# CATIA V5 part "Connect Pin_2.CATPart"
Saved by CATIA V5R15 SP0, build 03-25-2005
Part number: Connect Pin_2
Material "Light Green": density 7860 kg/m3, Young's modulus 2e+11 Pa, Poisson ratio 0.266
Bounding box of the stored display mesh (mm): x -29 to 29, y -75 to 79, z -29 to 29
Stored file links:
  E:\#01 CATIA Lecture Materials\#06 DMU\#11 DMU Page01 KIN EX11\Connect Pin_2.CATPart
  E:\V5_education\CATIA Data\KIN\Under Motor\Shaft_2.CATPart
  C:\Program Files\Dassault Systemes\B20\win_b64\startup\materials\Catalog.CATMaterial
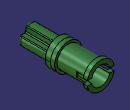
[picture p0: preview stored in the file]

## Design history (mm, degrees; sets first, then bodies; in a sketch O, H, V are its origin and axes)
Body1 (main body), material "Light Green"
  Sketch1 on xy-plane, origin (0, 0, 0), H (1, 0, 0), V (0, 1, 0)
    point P1 (0, 79)
    line L1 (0, 79) -> (29, 79)
    line L2 (29, 79) -> (29, 70)
    line L3 (29, 70) -> (24, 70)
    line L4 (24, 70) -> (24, 9)
    line L5 (24, 9) -> (29, 9)
    point P6 (29, 9)
    line L6 (29, 9) -> (29, 0)
    point P7 (29, 0)
    point P8 (29, 0)
    axis line L7 (0, -92.0572) -> (0, 94.0849)
    point P9 (0, -92.0572)
    line L8 (29, 0) -> (0, 0)
    distance L1 H = 79
    length L2 = 9
    length L6 = 9
    distance L2 V = 29
    distance L4 V = 24
    coincidence: P1 V, P6 L2, P7 H, P9 V, P7 P8
    horizontal: L1 H, L3 H, L5 H, L8 H
    vertical: L2 V, L4 V, L6 V, L7 V
    symmetry: P7 P8 H
  Shaft1: profile Sketch1, axis Sketch1.L7, angle 360
  Sketch2 on zx-plane, origin (0, 0, 0), H (1, 0, 0), V (0, 0, 1)
    circle A1 centre (0, 0) radius 20
    radius A1 = 20
  Pocket1: profile Sketch2, direction (0, 1, 0), through (limit type 3), opposite side length -9
  Sketch3 on yz-plane, origin (0, 0, 0), H (0, 1, 0), V (0, 0, 1)
    line L1 (50, 5) -> (79, 5)
    line L2 (79, 5) -> (79, -5)
    line L3 (79, -5) -> (50, -5)
    line L4 (50, -5) -> (50, 5)
    reference intersected line E1 (79, 29) -> (79, -29) from face of Shaft1 from Sketch1.L1
    distance L4 V = 50
    distance L3 L1 = 10
    horizontal: L1 H, L3 H
    vertical: L2 V, L4 V
    symmetry: L3 L1 H
    coincidence: L2 E1
  Pocket2: profile Sketch3, direction (-1, 0, 0), through (limit type 3), opposite side through (limit type 3)
  Sketch4 on face of Shaft1 from Sketch1.L8, origin (0, 0, 0), H (1, 0, 0), V (0, 0, 1)
    arc A1 centre (0, 0) radius 23.5 from (21.603, -9.25) to (21.603, 9.25) ccw
    line L1 (-21.603, 9.25) -> (-9.25, 9.25)
    line L2 (21.603, -9.25) -> (9.25, -9.25)
    line L3 (9.25, 21.603) -> (9.25, 9.25)
    line L4 (-9.25, -21.603) -> (-9.25, -9.25)
    point P4 (-9.25, -21.603)
    arc A2 centre (0, 0) radius 23.5 from (-9.25, -21.603) to (9.25, -21.603) ccw
    point P6 (-21.603, 9.25)
    arc A3 centre (0, 0) radius 23.5 from (-21.603, 9.25) to (-21.603, -9.25) ccw
    point P8 (9.25, 21.603)
    arc A4 centre (0, 0) radius 23.5 from (9.25, 21.603) to (-9.25, 21.603) ccw
    point P9 (-9.25, 9.25)
    line L5 (9.25, 9.25) -> (21.603, 9.25)
    line L6 (9.25, -9.25) -> (9.25, -21.603)
    line L7 (-9.25, 9.25) -> (-9.25, 21.603)
    point P12 (-9.25, -9.25)
    line L8 (-9.25, -9.25) -> (-21.603, -9.25)
    radius A1 = 23.5
    distance L1 L2 = 18.5
    distance H L1 = 9.25
    distance L3 L4 = 18.5
    distance V L3 = 9.25
    horizontal: L1 H, L2 H, L5 H, L8 H
    vertical: L3 V, L4 V, L6 V, L7 V
    coincidence: A1 P4, A1 A2, A1 P6, A1 A3, A1 P8, A1 A4, L4 P9, L1 L5, L3 L6, L2 P12, L4 L7, L2 L8
  Sketch5 on face of Shaft1 from Sketch1.L8, origin (0, 0, 0), H (1, 0, 0), V (0, 0, 1)
    circle A1 centre (0, 0) radius 29
    reference projected circle E1 centre (0, 0) radius 29 from edge [face of Shaft1 from Sketch1.L8 | face of Shaft1 from Sketch1.L6]
    coincidence: A1 E1
  Pad1: profile Sketch5, direction (0, -1, 0), length 11.4
  Pad2: profile Sketch4, direction (0, -1, 0), length 75
  Fillet1: radius 5, on edge [face of Pad2 from Sketch4.A2 | end face of Pad2]; edge [face of Pad2 from Sketch4.A1 | end face of Pad2]; edge [face of Pad2 from Sketch4.A4 | end face of Pad2]; edge [face of Pad2 from Sketch4.A3 | end face of Pad2]
  Fillet2: radius 2, on edge [face of Pad2 from Sketch4.L6 | face of Pad2 from Sketch4.A2]; edge [face of Pad2 from Sketch4.A2 | face of Pad2 from Sketch4.L4]; edge [face of Pad2 from Sketch4.L8 | face of Pad2 from Sketch4.A3]; edge [face of Pad2 from Sketch4.A1 | face of Pad2 from Sketch4.L2]; edge [face of Pad2 from Sketch4.L5 | face of Pad2 from Sketch4.A1]; edge [face of Pad2 from Sketch4.L2 | face of Pad2 from Sketch4.L6]; edge [face of Pad2 from Sketch4.A4 | face of Pad2 from Sketch4.L3]; edge [face of Pad2 from Sketch4.L4 | face of Pad2 from Sketch4.L8]; edge [face of Pad2 from Sketch4.L7 | face of Pad2 from Sketch4.A4]; edge [face of Pad2 from Sketch4.A3 | face of Pad2 from Sketch4.L1]; edge [face of Pad2 from Sketch4.L1 | face of Pad2 from Sketch4.L7]; edge [face of Pad2 from Sketch4.L3 | face of Pad2 from Sketch4.L5]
